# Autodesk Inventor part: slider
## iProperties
Created: 2009-04
Part Number: slider
Document SubType Name: Modeling
Designer: Lochan
Density: 1 g/cm^3
Author: Lochan
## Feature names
1. Extrusion1
2. Revolution1
